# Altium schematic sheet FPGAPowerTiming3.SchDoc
size B
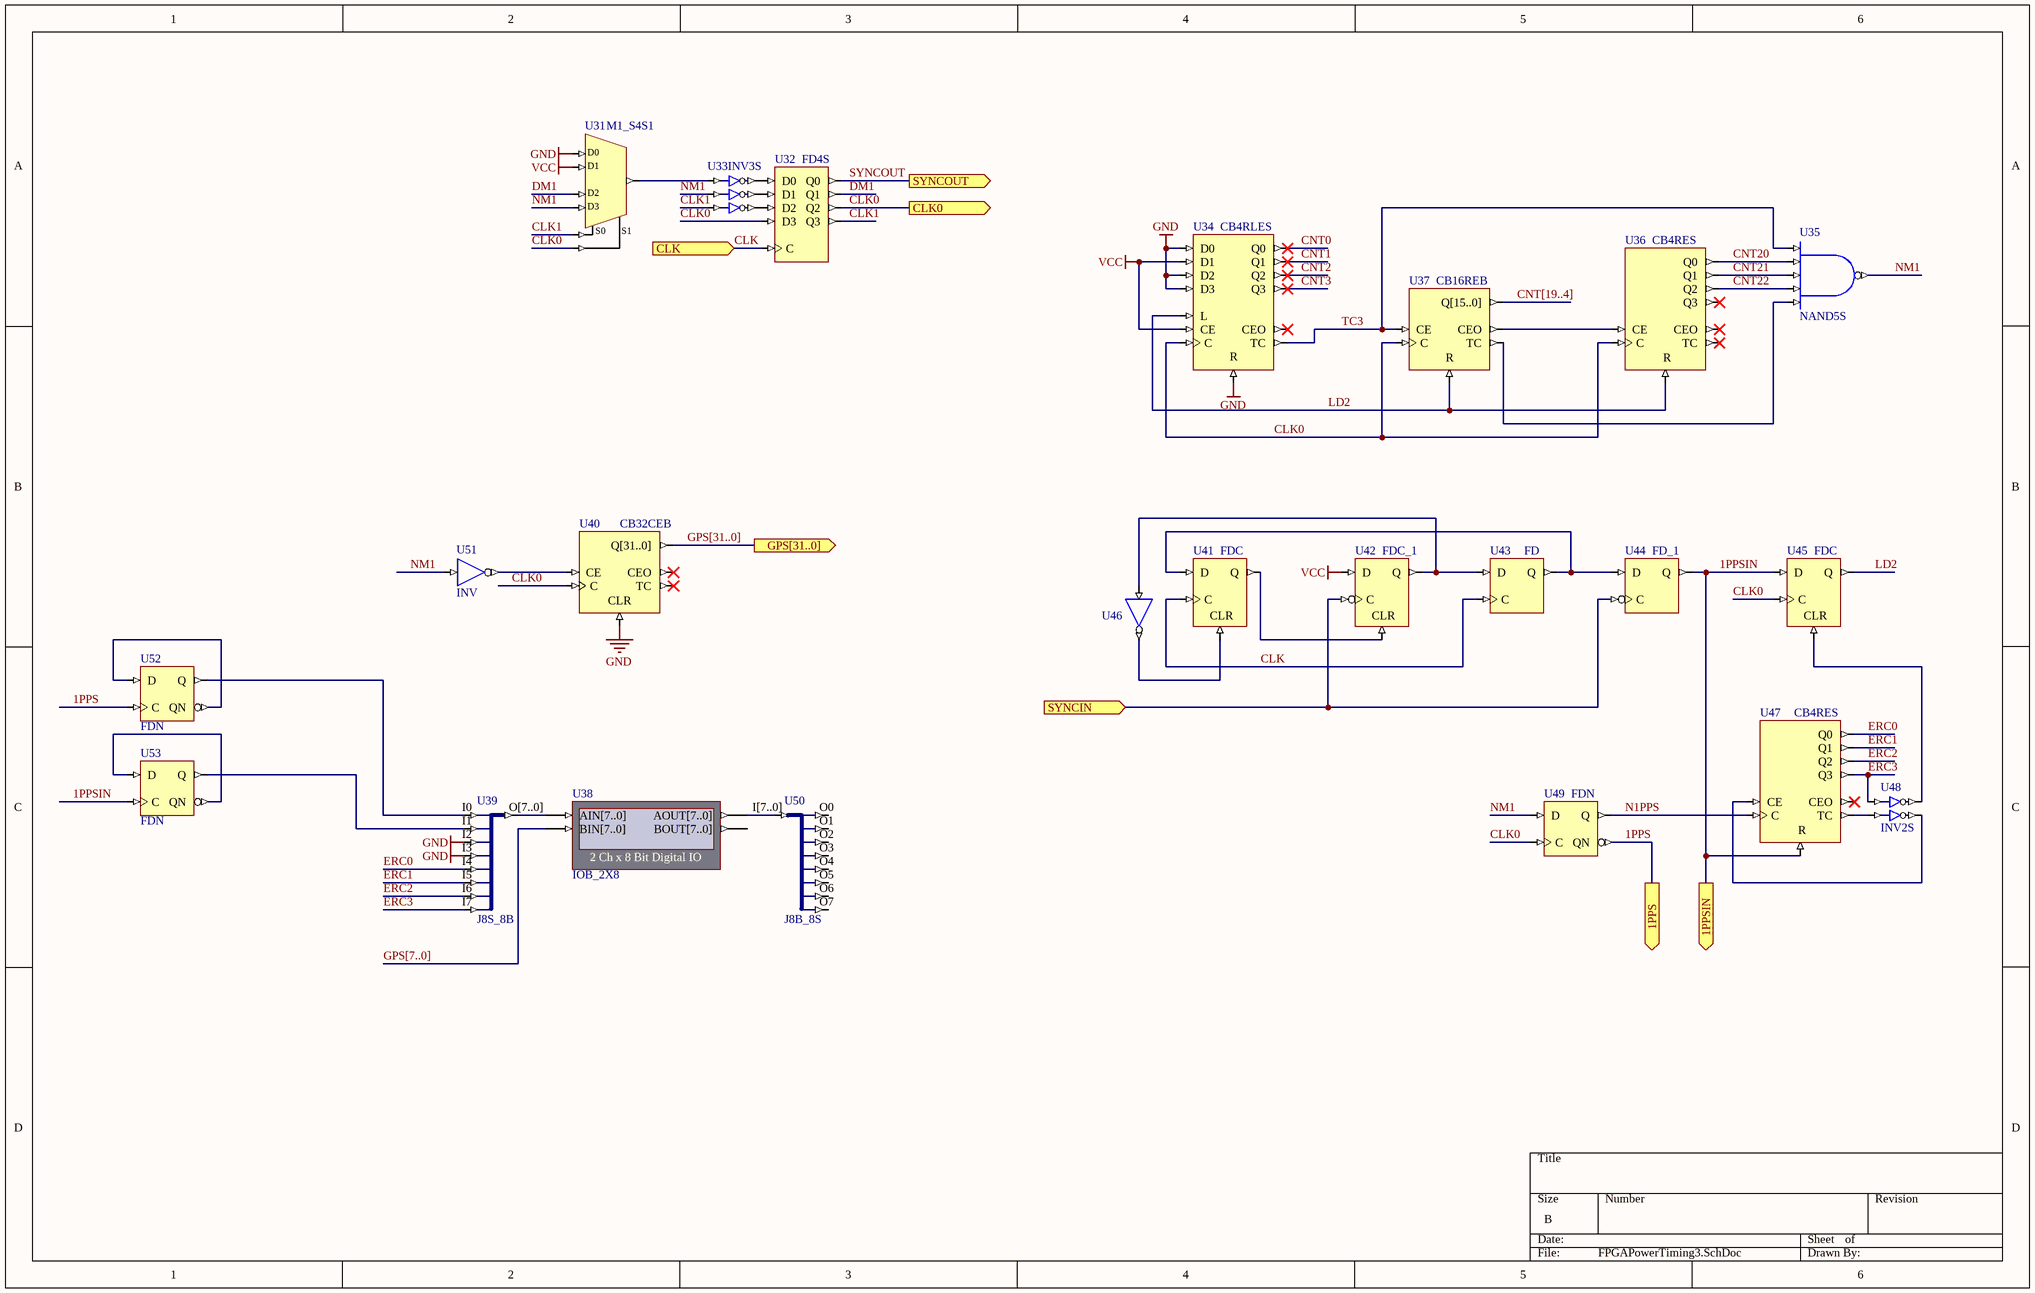
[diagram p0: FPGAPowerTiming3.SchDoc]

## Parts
U31  M1_S4S1
U32  FD4S
U33  INV3S
U34  CB4RLES
U35  NAND5S
U36  CB4RES
U37  CB16REB
U38  IOB_2X8
U39  J8S_8B
U40  CB32CEB
U41  FDC
U42  FDC_1
U43  FD
U44  FD_1
U45  FDC
U46  INV  (value not drawn)
U47  CB4RES
U48  INV2S
U49  FDN
U50  J8B_8S
U51  INV
U52  FDN
U53  FDN

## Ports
1PPS (out), 1PPSIN (out), CLK0 (out), CLK (in), GPS[31..0] (out), SYNCIN (in), SYNCOUT (out)

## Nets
GND: U31.D0 U34.D0 U34.D2 U34.D3 U34.R U39.I2 U39.I3 U40.CLR
VCC: U31.D1 U34.CE U34.D1 U42.D
1PPS: U49.QN U52.C ; port 1PPS
1PPSIN: U44.Q U45.D U47.R U53.C ; port 1PPSIN
CLK: U32.C U41.C U43.C ; port CLK
CLK0: U31.S1 U32.D3 U32.Q2 U34.C U36.C U37.C U40.C U45.C U49.C ; port CLK0
CLK1: U31.S0 U32.Q3 U33.I2
CNT0: U34.Q0
CNT1: U34.Q1
CNT2: U34.Q2
CNT3: U34.Q3
CNT20: U35.I1 U36.Q0
CNT21: U35.I2 U36.Q1
CNT22: U35.I3 U36.Q2
DM1: U31.D2 U32.Q1
ERC0: U39.I4 U47.Q0
ERC1: U39.I5 U47.Q1
ERC2: U39.I6 U47.Q2
ERC3: U39.I7 U47.Q3 U48.I0
LD2: U34.L U36.R U37.R U45.Q
N1PPS: U47.C U49.Q
NM1: U31.D3 U33.I1 U35.O U49.D U51.I
SYNCIN: U42.C U44.C ; port SYNCIN
SYNCOUT: U32.Q0 ; port SYNCOUT
TC3: U34.TC U35.I0 U37.CE
NetU31_O: U31.O U33.I0
NetU32_D0: U32.D0 U33.O0
NetU32_D1: U32.D1 U33.O1
NetU32_D2: U32.D2 U33.O2
NetU35_I4: U35.I4 U37.TC
NetU36_CE: U36.CE U37.CEO
NetU39_I0: U39.I0 U52.Q
NetU39_I1: U39.I1 U53.Q
NetU40_CE: U40.CE U51.O
NetU41_CLR: U41.CLR U46.O
NetU41_D: U41.D U43.Q U44.D
NetU41_Q: U41.Q U42.CLR
NetU42_Q: U42.Q U43.D U46.I
NetU45_CLR: U45.CLR U48.O0
NetU47_CE: U47.CE U48.O1
NetU47_TC: U47.TC U48.I1
NetU52_D: U52.D U52.QN
NetU53_D: U53.D U53.QN

Not connected (* = marked no-connect by the designer): U34 CEO*; U36 CEO* Q3* TC*; U37 Q[15..0]; U38 AIN[7..0] AOUT[7..0] BIN[7..0] BOUT[7..0]; U39 O[7..0]; U40 CEO* Q[31..0] TC*; U47 CEO*; U50 I[7..0] O0 O1 O2 O3 O4 O5 O6 O7

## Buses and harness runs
bus CNT[19..4]
bus GPS[7..0]
bus GPS[31..0] = port GPS[31..0]

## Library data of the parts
U31 = M1_S4S1: 4x1-Single Wire to 1x1-Single Wire Multiplexer; SubClass: SnS1; PortSize: 1; PortStyle: Single Pin Version; ArchiveName: GENERIC; VHDLIB_SIM: GENERIC_LIB
U32 = FD4S: 4-Bit D-Type Flip-Flop, Single Pin Version; XilinxEquivalent: FD4; SubClass: FD; ClockTrigger: Rising; PortSize: 4; ArchiveName: GENERIC; VHDLIB_SIM: GENERIC_LIB
U33 = INV3S: 3-Bit Inverter, Single Pin Version; FunctionalClass: Logic Primitive; SubClass: INV; PortSize: 3; ArchiveName: GENERIC; VHDLIB_SIM: GENERIC_LIB
U34 = CB4RLES: 4-Bit Loadable Cascadable Binary Counter with Clock Enable and Synchronous Reset, Single Pin Version; XilinxEquivalent: CB4RLE; ClockTrigger: Rising; Enable: High; Loadable: True; PortSize: 4; ArchiveName: GENERIC; VHDLIB_SIM: GENERIC_LIB
U35 = NAND5S: 5-Input NAND Gate, Single Pin Version; XilinxEquivalent: NAND5; FunctionalClass: Logic Primitive; PortSize: 5; ArchiveName: GENERIC; VHDLIB_SIM: GENERIC_LIB
U36 U47 = CB4RES: 4-Bit Cascadable Binary Counter with Clock Enable and Synchronous Reset, Single Pin Version; XilinxEquivalent: CB4RE; ClockTrigger: Rising; Enable: High; PortSize: 4; ArchiveName: GENERIC; VHDLIB_SIM: GENERIC_LIB
U37 = CB16REB: 16-Bit Cascadable Binary Counter with Clock Enable and Synchronous Reset, Bus Version; XilinxEquivalent: CB16RE; ClockTrigger: Rising; Enable: High; PortSize: 16; ArchiveName: GENERIC; VHDLIB_SIM: GENERIC_LIB
U38 = IOB_2X8: 2 Ch x 8 Bit Digital IO; NEXUS_CORE: Instrument; NEXUS_JTAG_DEVICE: True; NEXUS_JTAG_ORDER: 0
U39 = J8S_8B: 8 Single pin inputs to single 8-Bit output bus; FunctionalClass: Bus Joiner; PortSize: 8; ArchiveName: GENERIC; VHDLIB_SIM: GENERIC_LIB
U40 = CB32CEB: 32-Bit Cascadable Binary Counters with Clock Enable and Asynchronous Clear, Bus Version; ClockTrigger: Rising; Enable: High; PortSize: 32; ArchiveName: GENERIC; VHDLIB_SIM: GENERIC_LIB
U41 U45 = FDC: D-Type Flip-Flop with Asynchronous Clear; SubClass: FD; ClockTrigger: Rising; ArchiveName: GENERIC; VHDLIB_SIM: GENERIC_LIB
U42 = FDC_1: D-Type Negative Edge Flip-Flop with Asynchronous Clear; SubClass: FD; ClockTrigger: Falling; ArchiveName: GENERIC; VHDLIB_SIM: GENERIC_LIB
U43 = FD: D-Type Flip-Flop; ClockTrigger: Rising; ArchiveName: GENERIC; VHDLIB_SIM: GENERIC_LIB
U44 = FD_1: D-Type Negative Edge Flip-Flop; SubClass: FD; ClockTrigger: Falling; ArchiveName: GENERIC; VHDLIB_SIM: GENERIC_LIB
U46 U51 = INV: Inverter; FunctionalClass: Logic Primitive; ArchiveName: GENERIC; VHDLIB_SIM: GENERIC_LIB
U48 = INV2S: 2-Bit Inverter, Single Pin Version; XilinxEquivalent: INV2; FunctionalClass: Logic Primitive; SubClass: INV; PortSize: 2; ArchiveName: GENERIC; VHDLIB_SIM: GENERIC_LIB
U49 U52 U53 = FDN: D-Type Flip-Flop with Inverted and Non-Inverted Outputs; SubClass: FD; ClockTrigger: Rising; ArchiveName: GENERIC; VHDLIB_SIM: GENERIC_LIB
U50 = J8B_8S: 8-Bit input bus to 8 single pin outputs; FunctionalClass: Bus Joiner; PortSize: 8; ArchiveName: GENERIC; VHDLIB_SIM: GENERIC_LIB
